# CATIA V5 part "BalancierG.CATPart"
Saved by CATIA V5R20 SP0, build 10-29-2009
Part number: BalancierG
Bounding box of the stored display mesh (mm): x 0 to 1, y -1.662 to 0.749, z -7.043 to 0.749
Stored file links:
  D:\Dropbox\IAO_2012\IAO_2012_746_mderemetz\IAO_2012_746_mderemetz_Catia\BalancierG.CATPart
  D:\Dropbox\IAO_2012\IAO_2012_746_mderemetz\IAO_2012_746_mderemetz_Catia\mderemetz.CATProduct
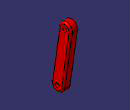
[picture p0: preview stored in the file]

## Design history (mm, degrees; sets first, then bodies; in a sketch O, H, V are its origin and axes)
External parameters (linked from other documents)
  External.AC = 3 mm
Set1
  Plane1 "Plan_Ref": linked copy from another document
  Point1 "G": linked copy from another document
  Point2 "E": linked copy from another document
  Plane2 "Plan_Sec": linked copy from another document
Body1 (main body)
  Sketch1 on Plane1, origin (0, 0, 0), H (0, 1, 0), V (0, 0, 1)
    construction line L1 (0, 0) -> (-0.9134, -6.2941)
    point P1 (0, 0)
    point P2 (-0.9134, -6.2941)
    line L2 (0.7422, -0.1077) -> (-0.1712, -6.4018)
    line L3 (-1.6556, -6.1864) -> (-0.7422, 0.1077)
    arc A1 centre (-0.9134, -6.2941) radius 0.75 from (-0.1712, -6.4018) to (-1.6556, -6.1864) cw
    arc A2 centre (0, 0) radius 0.75 from (-0.7422, 0.1077) to (0.7422, -0.1077) cw
    reference projected point E1 (0, 0) from Point1
    reference projected point E2 (-0.9134, -6.2941) from Point2
    distance L3 L2 = 1.5 {= 1.5*External.AC /3}
    tangency: A1 L2, A2 L2, A1 L3, A2 L3
    parallelism: L1 L2
    coincidence: P1 E1, P2 E2
  Pad1: profile Sketch1, direction (1, 0, 0), up to Plane2
  Sketch2 on end face of Pad1, origin (1, 1.6346, 5.0601), H (0, 1, 0), V (0, 0, 1)
    point P1 (-2.548, -11.3541)
    reference projected point E1 (-2.548, -11.3541) from Point2
    coincidence: P1 E1
  Hole1: placed by Sketch2, at (1, -0.9134, -6.2941) direction (-1, 0, 0), diameter 0.5 {= 0.5*External.AC /3}, through (limit type 3)
  Sketch3 on end face of Pad1, origin (1, 1.8319, 3.4187), H (0, 1, 0), V (0, 0, 1)
    point P1 (-1.8319, -3.4187)
    reference projected point E1 (-1.8319, -3.4187) from Point1
    coincidence: P1 E1
  Hole2: placed by Sketch3, at (1, 0, 0) direction (-1, 0, 0), diameter 0.5 {= 0.5*External.AC /3}, through (limit type 3)
  Fillet1: radius 0.2 {= 0.2*External.AC /3}, on edge [end face of Pad1 | face of Pad1 from Sketch1.L2]; edge [start face of Pad1 | face of Pad1 from Sketch1.L2]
